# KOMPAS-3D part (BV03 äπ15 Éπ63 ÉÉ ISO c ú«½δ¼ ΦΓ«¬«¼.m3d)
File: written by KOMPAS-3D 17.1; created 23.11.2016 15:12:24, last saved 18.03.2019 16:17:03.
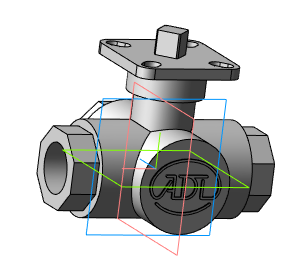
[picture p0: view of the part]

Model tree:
1. Операция без истории:2  (labels: Сталь 20  ГОСТ 1050-88)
